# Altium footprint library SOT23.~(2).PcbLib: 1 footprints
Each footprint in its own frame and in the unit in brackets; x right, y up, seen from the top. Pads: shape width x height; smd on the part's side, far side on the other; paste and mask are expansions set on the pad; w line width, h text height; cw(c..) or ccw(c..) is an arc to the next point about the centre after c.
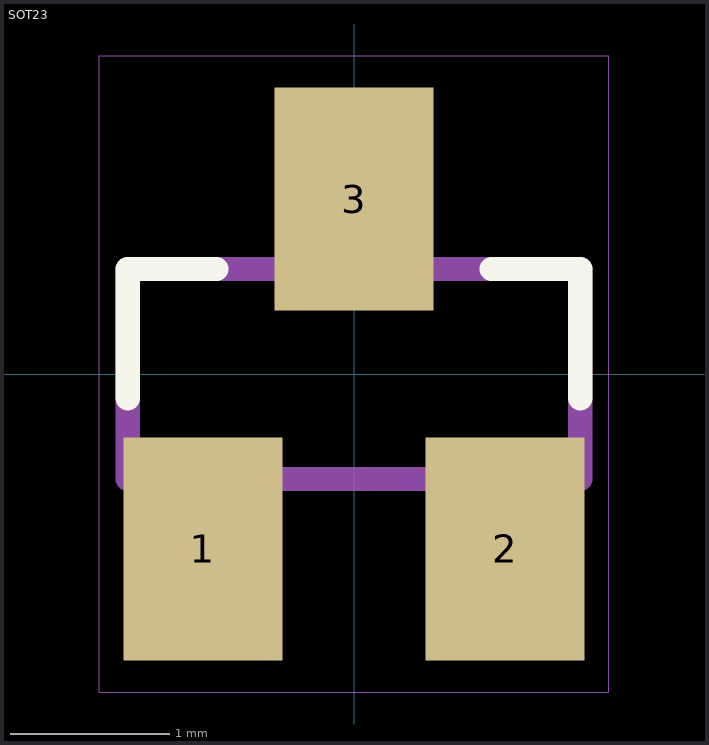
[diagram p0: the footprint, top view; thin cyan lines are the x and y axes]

## SOT23 [mm]
pads (3):
  rect 1x1.4 smd: 1(-0.95,-1.1) 2(0.95,-1.1) 3(0,1.1)
Top Overlay:
  lines w0.152: -1.422,-0.152 -1.422,0.66 -0.864,0.66 ; 0.864,0.66 1.422,0.66 1.422,-0.152
Assembly Top:
  region: -0.711,-1.295 -1.168,-1.295 -1.168,-0.711 -0.711,-0.711
  region: 1.168,-1.295 0.711,-1.295 0.711,-0.711 1.168,-0.711
  region: 0.229,0.711 -0.229,0.711 -0.229,1.295 0.229,1.295
  lines w0.152: -1.422,-0.66 -1.422,0.66 1.422,0.66 1.422,-0.66 -1.422,-0.66
Courtyard Top:
  lines w0: -1.6,-2 -1.6,2 1.6,2 1.6,-2 -1.6,-2
3D body "step_temp.STEP": height 1.12, standoff 0, extent -1.472,-1.125 1.448,1.245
